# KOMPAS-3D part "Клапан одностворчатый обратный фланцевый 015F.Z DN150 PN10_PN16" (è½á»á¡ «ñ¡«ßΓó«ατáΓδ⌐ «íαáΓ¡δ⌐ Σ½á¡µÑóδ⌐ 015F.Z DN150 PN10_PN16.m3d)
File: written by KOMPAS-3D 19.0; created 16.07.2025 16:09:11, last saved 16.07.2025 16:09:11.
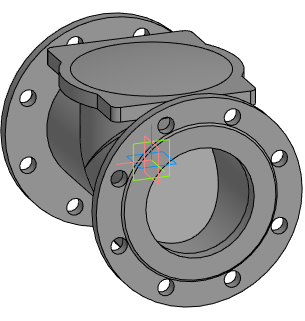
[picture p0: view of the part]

Document properties: Полное имя файла: E:\Dendor Работа Сачек\3D для проектировщиков\5.4 Тип 015F.Z. Клапан одностворчатый обратный фланцевый\stp_Клапан одностворчатый обратный фланцевый 015F.Z PN10_16\Клапан одностворчатый обратный фланцевый 015F.Z DN150 PN10_PN16.m3d

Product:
- Part/product: Клапан одностворчатый обратный фланцевый 015F.Z DN150 PN10_PN16

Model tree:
1. Операция без истории:1
2. Операция без истории:2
